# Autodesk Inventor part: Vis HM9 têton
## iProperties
Created: 2002-06
Part Number: Vis HM9 têton
Material: Par défaut
Catalog Web Link: www.traceparts.com
Description: Vis tête hexagonale DIN 561 - B M20x2x40 - 5,6
Document SubType Name: Modélisation
Designer: REVEST Pierre
Control State: 0
Master: False
Checked Out: False
Shininess: 20.0
Length Units: 11269
Angle Units: 11279
Time Units: 11290
Mass Units: 11283
Length Display Precision: 3
Angle Display Precision: 2
Density: 0.0
Volumn: 0.0
Area: 0.0
PropertySet Name: Model Information
Author: REVEST Pierre
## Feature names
1. Base1
